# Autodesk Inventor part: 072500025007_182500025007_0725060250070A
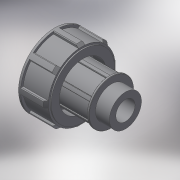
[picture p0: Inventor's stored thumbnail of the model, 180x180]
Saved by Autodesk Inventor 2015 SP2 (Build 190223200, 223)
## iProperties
Created: 2017-04
Part Number: 072500025007_182500025007_0725060250070A
Material: Generic
Description: PLASSON THREADED ADAPTOR 25-3/4"
Document SubType Name: Modeling
Designer: KIM
Density: 1 g/cm^3
Appearance: Default
Author: KIM
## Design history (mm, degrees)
derived "07250.ipt"
feature "Solid1::07250.ipt"
tag "TaggingFeature1"
body "Solid1"
other parameters: "d1" = 26.441, "d3" = 18, "d6" = 54, "d7" = 50.22, "d8" = 43.2, "d9" = 25, "d10" = 31.7292, "d12" = 15.8646, "d13" = 21.1528, "d14" = 20.7, "d15" = 40.5, "d16" = 2.4, "d17" = 32, "d18" = 18, "d19" = 21.6, "d24" = 5.2882, "d25" = 2.6441, "d27" = 0, "d28" = 2.11528, "d31" = 0.52882, "d35" = 360 deg, "d41" = 29.337, "d56" = 27.5, "d57" = 2.5, "d58" = 1.25, "d60" = 0, "d61" = 0.26441, "d64" = 0.26441, "d68" = 360 deg, "d_" = 25, "R_" = 26.441, "E_" = 54, "l_2" = 18, "d55" = 25
